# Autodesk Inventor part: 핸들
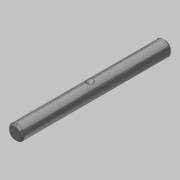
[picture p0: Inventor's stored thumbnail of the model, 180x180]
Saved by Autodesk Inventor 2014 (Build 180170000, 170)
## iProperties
Created: 2019-04
Part Number: 핸들
Material: 스테인리스강
Document SubType Name: Modeling
Designer: mduedu
Density: 1 g/cm^3
Appearance: 반광택
Author: mduedu
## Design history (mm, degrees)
sketch "스케치1"
  geometry: C1 r 4 at (0, 0); 1 further point
  constraints: 1 centre point, 1 coincident
  dimensions: "d0" = 8 diameter of C1
extrude "돌출1" new body sketch "스케치1" stored distance "d1" = 80; taper "d2" = 0 deg
chamfer "모따기1" distance "d3" = 1; stored, may be unused: second distance "d4" = 2, angle "d5" = 45 deg
sketch "스케치2"
  geometry: L1 (-39, 4)-(39, 4) reference; L2 (0, 4)-(0, 2); L3 (0, 2)-(2, 4); L4 (0, 4)-(2, 4); 1 further point
  constraints: 6 end point, 2 perpendicular, 1 midpoint, 1 point on line
  dimensions: "d6" = 4 diameter of L3.end L2; "d8" = 45 deg angle of L3 L2
revolve "회전1" sketch "스케치2" stored, may be unused: angle "d10" = 90 deg
node "작업점1"
  node "작업축1"
  node "작업 평면1"
node "솔리드1"
